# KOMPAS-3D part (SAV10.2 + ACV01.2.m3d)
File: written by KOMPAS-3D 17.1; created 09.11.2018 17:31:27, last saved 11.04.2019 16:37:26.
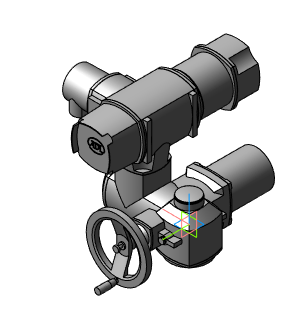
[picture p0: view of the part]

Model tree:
1. Операция без истории:2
